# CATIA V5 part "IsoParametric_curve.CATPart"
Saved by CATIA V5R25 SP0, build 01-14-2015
Part number: Part1
Bounding box of the stored display mesh (mm): x -201.73 to 99, y -122.834 to 226.104, z -13.817 to 30.795
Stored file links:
  E:\cadcim\GSD_cat_v5-6r2014\Part_files\IsoParametric_curve.CATPart
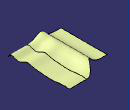
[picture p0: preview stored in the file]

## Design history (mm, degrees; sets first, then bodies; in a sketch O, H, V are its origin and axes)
Body1 (main body)
  Sketch1 on yz-plane, origin (0, 0, 0), H (0, 1, 0), V (0, 0, 1)
    spline S1 through (-122.8344, -6.7669) (-106.6526, 10.0033) (-67.8164, 0) (-14.2694, 18.5355) (14.5636, 14.4165) (64.8742, 7.0611) (133.1319, 3.8248) (184.3252, 10.0033) (226.1036, 7.0611)
    point P1 (-67.8164, 0)
    coincidence: P1 H
  Extrude1: Lim1 99, Lim2 0, Element1 Sketch1
  Sketch2 on zx-plane, origin (0, 0, 0), H (-1, 0, 0), V (0, 0, 1)
    spline S1 through (107.3762, 13.3919) (140.5417, -9.862) (187.902, -13.8052) (201.7301, -13.8052)
  Extrude2: Lim1 122, Lim2 142, Element1 Sketch2
  Blend1: StartLimit {blendlimit Curve edge of Extrude2, Support Extrude2}, EndLimit {blendlimit Curve Sketch1, Support Extrude1}
  Join1: Elements (Extrude2; Blend1; Extrude1)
